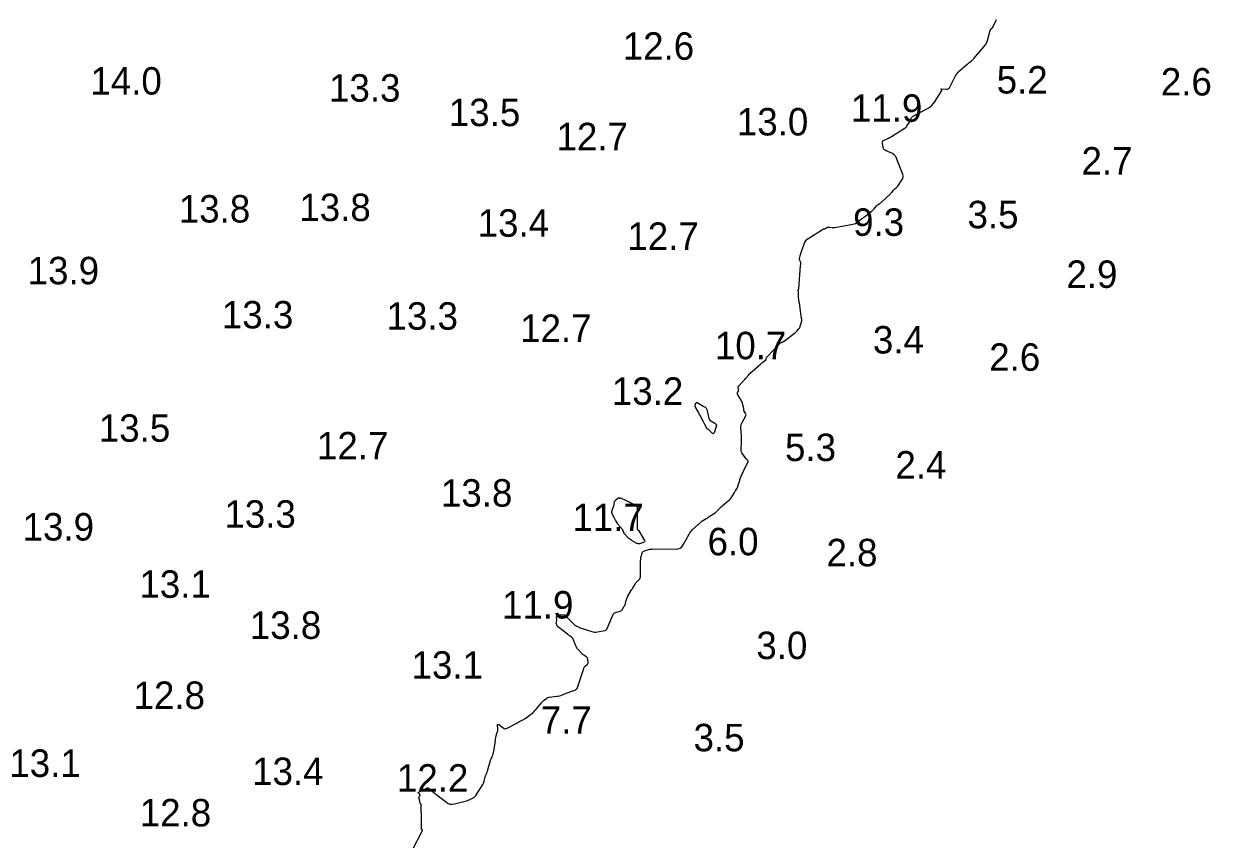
# Model space of a CAD drawing. Extents: x 815352 to 820877, y 582403 to 597439.
# Drawn here: x 819635.6 to 819851.7, y 588299.8 to 588448.3 of the extents above; entities that cross this region are included whole.
import ezdxf

# ---------------------------------------------------------------- set-up
doc = ezdxf.new("R2010")
doc.units = 0
doc.layers.add('V-CONT-EL12', color=7, linetype='Continuous')
doc.layers.add('V-TOPO-SOUN', color=7, linetype='Continuous')

msp = doc.modelspace()

# ---------------------------------------------------------------- linework, layer by layer
at = {"layer": 'V-CONT-EL12'}
msp.add_lwpolyline([(819706.36, 588297.79), (819708.22, 588301.4), (819708.23, 588301.44), (819708.23, 588301.46), (819708.22, 588301.49), (819708.2, 588301.52), (819708.08, 588301.61), (819708.05, 588301.63), (819708.03, 588301.66), (819708.02, 588301.69), (819708.02, 588301.73), (819708.05, 588302.47), (819708.05, 588302.6), (819708.06, 588302.74), (819708.06, 588302.87), (819708.05, 588303.01), (819707.95, 588306.19), (819707.95, 588306.21), (819707.94, 588306.23), (819707.93, 588306.25), (819707.91, 588306.27), (819707.83, 588306.32), (819707.81, 588306.34), (819707.79, 588306.36), (819707.78, 588306.38), (819707.77, 588306.4), (819707.58, 588307.28), (819707.57, 588307.34), (819707.57, 588307.4), (819707.59, 588307.47), (819707.61, 588307.53), (819707.74, 588307.77), (819707.76, 588307.82), (819707.76, 588307.88), (819707.75, 588307.93), (819707.71, 588307.98), (819707.49, 588308.22), (819707.45, 588308.28), (819707.45, 588308.33), (819707.47, 588308.37), (819707.52, 588308.4), (819709.02, 588309.14), (819709.06, 588309.16), (819709.09, 588309.16), (819709.13, 588309.16), (819709.17, 588309.16), (819709.33, 588309.11), (819709.37, 588309.09), (819709.4, 588309.07), (819709.44, 588309.05), (819709.47, 588309.03), (819710.27, 588308.34), (819710.42, 588308.21), (819710.56, 588308.09), (819710.71, 588307.97), (819710.86, 588307.86), (819712.56, 588306.55), (819712.9, 588306.34), (819713.26, 588306.22), (819713.64, 588306.19), (819714.04, 588306.25), (819716.24, 588306.83), (819716.4, 588306.88), (819716.55, 588306.93), (819716.71, 588306.99), (819716.85, 588307.06), (819717.45, 588307.35), (819717.59, 588307.44), (819717.71, 588307.53), (819717.82, 588307.65), (819717.92, 588307.78), (819719.18, 588309.77), (819719.26, 588309.91), (819719.33, 588310.06), (819719.39, 588310.22), (819719.44, 588310.38), (819719.62, 588311.11), (819719.65, 588311.23), (819719.69, 588311.35), (819719.73, 588311.46), (819719.77, 588311.58), (819719.97, 588312.03), (819720.02, 588312.15), (819720.06, 588312.26), (819720.1, 588312.38), (819720.14, 588312.5), (819720.54, 588313.94), (819720.58, 588314.08), (819720.63, 588314.21), (819720.68, 588314.35), (819720.73, 588314.48), (819720.96, 588315.02), (819721.01, 588315.15), (819721.05, 588315.29), (819721.09, 588315.43), (819721.12, 588315.57), (819721.42, 588317.33), (819721.44, 588317.47), (819721.47, 588317.6), (819721.49, 588317.74), (819721.51, 588317.88), (819721.6, 588318.45), (819721.62, 588318.58), (819721.65, 588318.7), (819721.68, 588318.83), (819721.72, 588318.95), (819721.87, 588319.44), (819721.91, 588319.56), (819721.93, 588319.69), (819721.93, 588319.81), (819721.93, 588319.94), (819721.88, 588320.57), (819721.89, 588320.69), (819721.93, 588320.75), (819722, 588320.75), (819722.1, 588320.7), (819722.92, 588320.1), (819723.1, 588320), (819723.28, 588319.96), (819723.47, 588319.98), (819723.66, 588320.05), (819725.28, 588320.93), (819725.43, 588321.01), (819725.58, 588321.1), (819725.74, 588321.18), (819725.89, 588321.26), (819726.51, 588321.58), (819726.66, 588321.66), (819726.81, 588321.75), (819726.96, 588321.85), (819727.1, 588321.95), (819728.14, 588322.75), (819728.35, 588322.92), (819728.55, 588323.11), (819728.75, 588323.3), (819728.93, 588323.51), (819729.92, 588324.73), (819730.02, 588324.84), (819730.12, 588324.94), (819730.23, 588325.04), (819730.34, 588325.13), (819730.81, 588325.48), (819730.94, 588325.56), (819731.06, 588325.62), (819731.2, 588325.67), (819731.34, 588325.69), (819732.65, 588325.86), (819732.9, 588325.89), (819733.15, 588325.95), (819733.39, 588326.02), (819733.63, 588326.1), (819734.74, 588326.53), (819734.9, 588326.59), (819735.06, 588326.65), (819735.22, 588326.71), (819735.38, 588326.77), (819736.02, 588327), (819736.16, 588327.07), (819736.28, 588327.17), (819736.38, 588327.29), (819736.44, 588327.44), (819737.57, 588330.94), (819737.62, 588331.06), (819737.68, 588331.17), (819737.76, 588331.27), (819737.86, 588331.36), (819738.26, 588331.71), (819738.34, 588331.8), (819738.39, 588331.9), (819738.41, 588332.02), (819738.4, 588332.14), (819738.24, 588332.81), (819738.2, 588332.91), (819738.15, 588333), (819738.08, 588333.07), (819737.98, 588333.13), (819737.58, 588333.34), (819737.49, 588333.4), (819737.4, 588333.46), (819737.31, 588333.54), (819737.24, 588333.62), (819736.55, 588334.4), (819736.45, 588334.52), (819736.36, 588334.65), (819736.28, 588334.78), (819736.22, 588334.92), (819735.91, 588335.63), (819735.87, 588335.7), (819735.84, 588335.78), (819735.81, 588335.86), (819735.78, 588335.93), (819735.66, 588336.24), (819735.63, 588336.31), (819735.59, 588336.38), (819735.53, 588336.44), (819735.47, 588336.49), (819735.03, 588336.85), (819734.93, 588336.92), (819734.84, 588337), (819734.74, 588337.07), (819734.64, 588337.15), (819733.06, 588338.36), (819733.01, 588338.4), (819732.97, 588338.43), (819732.94, 588338.47), (819732.9, 588338.52), (819732.76, 588338.7), (819732.73, 588338.74), (819732.71, 588338.78), (819732.69, 588338.81), (819732.67, 588338.85), (819732.61, 588339.01), (819732.6, 588339.05), (819732.59, 588339.09), (819732.59, 588339.13), (819732.59, 588339.17), (819732.68, 588339.68), (819732.69, 588339.74), (819732.69, 588339.79), (819732.68, 588339.85), (819732.67, 588339.91), (819732.61, 588340.13), (819732.6, 588340.18), (819732.61, 588340.24), (819732.62, 588340.29), (819732.65, 588340.33), (819732.84, 588340.57), (819732.88, 588340.61), (819732.93, 588340.64), (819732.98, 588340.66), (819733.04, 588340.67), (819733.28, 588340.67), (819733.35, 588340.67), (819733.41, 588340.68), (819733.47, 588340.68), (819733.53, 588340.69), (819733.88, 588340.72), (819733.96, 588340.72), (819734.03, 588340.71), (819734.09, 588340.68), (819734.15, 588340.63), (819734.65, 588340.14), (819734.75, 588340.04), (819734.85, 588339.94), (819734.95, 588339.84), (819735.05, 588339.74), (819735.97, 588338.83), (819736.04, 588338.77), (819736.11, 588338.72), (819736.19, 588338.67), (819736.27, 588338.63), (819736.6, 588338.48), (819736.68, 588338.45), (819736.76, 588338.41), (819736.85, 588338.38), (819736.93, 588338.35), (819739.03, 588337.65), (819739.29, 588337.58), (819739.55, 588337.54), (819739.81, 588337.55), (819740.08, 588337.58), (819741.5, 588337.86), (819741.58, 588337.89), (819741.65, 588337.93), (819741.71, 588337.98), (819741.75, 588338.04), (819741.98, 588338.46), (819741.99, 588338.48), (819742, 588338.49), (819742, 588338.5), (819742.01, 588338.52), (819742.04, 588338.59), (819742.05, 588338.62), (819742.06, 588338.63), (819742.87, 588340.63), (819742.95, 588340.8), (819743.07, 588340.93), (819743.21, 588341.03), (819743.39, 588341.11), (819744.21, 588341.35), (819744.36, 588341.4), (819744.48, 588341.48), (819744.58, 588341.59), (819744.67, 588341.72), (819744.97, 588342.27), (819745.04, 588342.41), (819745.1, 588342.56), (819745.16, 588342.7), (819745.2, 588342.86), (819745.37, 588343.5), (819745.42, 588343.65), (819745.48, 588343.8), (819745.54, 588343.95), (819745.62, 588344.09), (819746.3, 588345.24), (819746.38, 588345.37), (819746.46, 588345.5), (819746.54, 588345.63), (819746.62, 588345.76), (819746.93, 588346.28), (819747.02, 588346.41), (819747.1, 588346.52), (819747.2, 588346.64), (819747.3, 588346.74), (819747.72, 588347.16), (819747.81, 588347.27), (819747.88, 588347.4), (819747.92, 588347.53), (819747.93, 588347.67), (819747.95, 588350.62), (819747.96, 588350.79), (819747.98, 588350.96), (819748.01, 588351.13), (819748.05, 588351.29), (819748.23, 588351.94), (819748.29, 588352.09), (819748.38, 588352.21), (819748.5, 588352.3), (819748.65, 588352.36), (819749.41, 588352.58), (819749.59, 588352.62), (819749.78, 588352.65), (819749.96, 588352.67), (819750.15, 588352.68), (819754.33, 588352.66), (819754.75, 588352.7), (819755.12, 588352.85), (819755.43, 588353.1), (819755.68, 588353.45), (819756.76, 588355.39), (819756.9, 588355.61), (819757.05, 588355.82), (819757.22, 588356.01), (819757.4, 588356.2), (819758.44, 588357.13), (819758.51, 588357.19), (819758.57, 588357.25), (819758.64, 588357.31), (819758.7, 588357.37), (819758.95, 588357.61), (819759.02, 588357.67), (819759.08, 588357.72), (819759.15, 588357.78), (819759.23, 588357.82), (819759.91, 588358.23), (819760.05, 588358.31), (819760.18, 588358.39), (819760.32, 588358.48), (819760.45, 588358.57), (819761.53, 588359.29), (819761.63, 588359.36), (819761.73, 588359.44), (819761.82, 588359.53), (819761.9, 588359.62), (819762.23, 588360), (819762.32, 588360.09), (819762.41, 588360.18), (819762.5, 588360.26), (819762.59, 588360.34), (819763.96, 588361.48), (819764.11, 588361.62), (819764.24, 588361.76), (819764.37, 588361.92), (819764.48, 588362.08), (819765.02, 588362.95), (819765.06, 588363.03), (819765.11, 588363.1), (819765.16, 588363.18), (819765.21, 588363.25), (819765.4, 588363.55), (819765.45, 588363.62), (819765.49, 588363.7), (819765.53, 588363.78), (819765.56, 588363.86), (819766.16, 588365.63), (819766.27, 588365.95), (819766.39, 588366.26), (819766.53, 588366.57), (819766.67, 588366.88), (819767.51, 588368.62), (819767.53, 588368.66), (819767.53, 588368.71), (819767.51, 588368.75), (819767.48, 588368.79), (819767.33, 588368.94), (819767.3, 588368.97), (819767.26, 588369.01), (819767.23, 588369.05), (819767.19, 588369.09), (819766.5, 588369.99), (819766.39, 588370.16), (819766.31, 588370.34), (819766.27, 588370.53), (819766.26, 588370.73), (819766.31, 588372.14), (819766.32, 588372.44), (819766.31, 588372.74), (819766.3, 588373.05), (819766.29, 588373.35), (819766.19, 588374.72), (819766.19, 588374.98), (819766.23, 588375.24), (819766.3, 588375.48), (819766.41, 588375.72), (819767.08, 588376.9), (819767.13, 588377), (819767.14, 588377.11), (819767.12, 588377.21), (819767.08, 588377.32), (819766.75, 588377.89), (819766.73, 588377.92), (819766.73, 588377.95), (819766.72, 588377.98), (819766.73, 588378.01), (819766.76, 588378.14), (819766.76, 588378.17), (819766.77, 588378.2), (819766.76, 588378.24), (819766.76, 588378.27), (819766.52, 588379.17), (819766.47, 588379.33), (819766.41, 588379.49), (819766.34, 588379.64), (819766.26, 588379.78), (819765.62, 588380.78), (819765.57, 588380.86), (819765.55, 588380.95), (819765.56, 588381.04), (819765.58, 588381.13), (819765.75, 588381.55), (819765.77, 588381.61), (819765.78, 588381.68), (819765.78, 588381.74), (819765.76, 588381.81), (819765.7, 588382.08), (819765.69, 588382.14), (819765.7, 588382.2), (819765.73, 588382.26), (819765.76, 588382.31), (819766.56, 588383.15), (819766.7, 588383.3), (819766.84, 588383.46), (819766.98, 588383.61), (819767.11, 588383.77), (819767.65, 588384.4), (819767.79, 588384.56), (819767.93, 588384.71), (819768.08, 588384.85), (819768.23, 588384.99), (819769.77, 588386.34), (819769.87, 588386.43), (819769.97, 588386.51), (819770.07, 588386.59), (819770.18, 588386.67), (819770.71, 588387.07), (819770.75, 588387.11), (819770.78, 588387.15), (819770.81, 588387.2), (819770.82, 588387.25), (819770.87, 588387.47), (819770.88, 588387.53), (819770.91, 588387.58), (819770.94, 588387.62), (819770.97, 588387.67), (819773.27, 588390.1), (819773.3, 588390.13), (819773.33, 588390.15), (819773.37, 588390.18), (819773.41, 588390.2), (819773.56, 588390.28), (819773.6, 588390.3), (819773.64, 588390.32), (819773.68, 588390.34), (819773.72, 588390.36), (819773.9, 588390.44), (819773.95, 588390.46), (819773.99, 588390.48), (819774.03, 588390.51), (819774.07, 588390.54), (819775.99, 588391.98), (819776.1, 588392.07), (819776.2, 588392.16), (819776.3, 588392.25), (819776.4, 588392.35), (819776.77, 588392.77), (819776.85, 588392.88), (819776.92, 588392.99), (819776.98, 588393.11), (819777.02, 588393.24), (819777.22, 588393.96), (819777.26, 588394.13), (819777.28, 588394.29), (819777.28, 588394.46), (819777.27, 588394.63), (819776.95, 588396.95), (819776.93, 588397.12), (819776.9, 588397.3), (819776.87, 588397.47), (819776.84, 588397.64), (819776.69, 588398.51), (819776.67, 588398.59), (819776.67, 588398.68), (819776.67, 588398.76), (819776.67, 588398.85), (819776.7, 588399.23), (819776.7, 588399.3), (819776.7, 588399.36), (819776.69, 588399.42), (819776.68, 588399.48), (819776.63, 588399.79), (819776.63, 588399.82), (819776.63, 588399.85), (819776.64, 588399.88), (819776.65, 588399.91), (819776.72, 588400.02), (819776.73, 588400.05), (819776.74, 588400.08), (819776.75, 588400.11), (819776.76, 588400.14), (819777.08, 588404.22), (819777.08, 588404.27), (819777.08, 588404.32), (819777.09, 588404.37), (819777.1, 588404.42), (819777.12, 588404.63), (819777.12, 588404.68), (819777.12, 588404.73), (819777.11, 588404.77), (819777.1, 588404.82), (819776.94, 588405.22), (819776.92, 588405.31), (819776.9, 588405.39), (819776.9, 588405.48), (819776.91, 588405.56), (819777, 588406.04), (819777.02, 588406.15), (819777.05, 588406.26), (819777.08, 588406.37), (819777.11, 588406.47), (819777.74, 588408.25), (819777.88, 588408.56), (819778.07, 588408.84), (819778.3, 588409.08), (819778.57, 588409.29), (819781.07, 588410.86), (819781.12, 588410.89), (819781.16, 588410.91), (819781.21, 588410.93), (819781.26, 588410.95), (819781.47, 588411), (819781.53, 588411.01), (819781.58, 588411.03), (819781.63, 588411.05), (819781.67, 588411.08), (819781.99, 588411.26), (819782.06, 588411.29), (819782.14, 588411.31), (819782.21, 588411.32), (819782.29, 588411.31), (819782.83, 588411.24), (819782.94, 588411.23), (819783.06, 588411.23), (819783.18, 588411.23), (819783.29, 588411.25), (819786.6, 588411.81), (819786.83, 588411.86), (819787.05, 588411.94), (819787.25, 588412.05), (819787.45, 588412.19), (819788.2, 588412.78), (819788.39, 588412.93), (819788.58, 588413.08), (819788.77, 588413.23), (819788.96, 588413.37), (819790.01, 588414.19), (819790.13, 588414.28), (819790.24, 588414.39), (819790.35, 588414.5), (819790.45, 588414.61), (819790.91, 588415.17), (819790.98, 588415.24), (819791.04, 588415.31), (819791.11, 588415.36), (819791.19, 588415.42), (819791.51, 588415.62), (819791.58, 588415.67), (819791.66, 588415.72), (819791.73, 588415.78), (819791.8, 588415.84), (819793.44, 588417.38), (819793.52, 588417.45), (819793.59, 588417.53), (819793.66, 588417.6), (819793.73, 588417.68), (819794.02, 588418.03), (819794.08, 588418.1), (819794.14, 588418.16), (819794.2, 588418.22), (819794.27, 588418.27), (819794.54, 588418.49), (819794.6, 588418.54), (819794.66, 588418.6), (819794.72, 588418.67), (819794.77, 588418.74), (819795.57, 588419.94), (819795.69, 588420.17), (819795.75, 588420.4), (819795.74, 588420.65), (819795.68, 588420.89), (819794.56, 588423.87), (819794.43, 588424.13), (819794.27, 588424.35), (819794.06, 588424.53), (819793.81, 588424.67), (819792.53, 588425.24), (819792.37, 588425.34), (819792.25, 588425.46), (819792.16, 588425.61), (819792.12, 588425.79), (819792, 588426.59), (819792, 588426.77), (819792.05, 588426.92), (819792.14, 588427.04), (819792.29, 588427.13), (819792.98, 588427.45), (819793.16, 588427.53), (819793.32, 588427.62), (819793.49, 588427.71), (819793.65, 588427.81), (819795.96, 588429.26), (819796.1, 588429.35), (819796.23, 588429.46), (819796.34, 588429.58), (819796.45, 588429.71), (819796.93, 588430.35), (819796.99, 588430.43), (819797.04, 588430.52), (819797.08, 588430.61), (819797.11, 588430.71), (819797.23, 588431.11), (819797.27, 588431.2), (819797.32, 588431.28), (819797.39, 588431.35), (819797.47, 588431.41), (819800.32, 588432.96), (819800.66, 588433.18), (819800.97, 588433.43), (819801.24, 588433.73), (819801.48, 588434.05), (819802.77, 588436.06), (819802.78, 588436.1), (819802.79, 588436.14), (819802.79, 588436.18), (819802.77, 588436.22), (819802.69, 588436.38), (819802.68, 588436.42), (819802.68, 588436.44), (819802.7, 588436.46), (819802.74, 588436.46), (819803.68, 588436.4), (819803.84, 588436.41), (819803.98, 588436.46), (819804.09, 588436.55), (819804.18, 588436.68), (819805.21, 588438.71), (819805.37, 588439), (819805.57, 588439.28), (819805.79, 588439.53), (819806.04, 588439.77), (819807.41, 588440.94), (819807.51, 588441.02), (819807.61, 588441.11), (819807.71, 588441.19), (819807.82, 588441.27), (819808.23, 588441.6), (819808.33, 588441.69), (819808.43, 588441.78), (819808.52, 588441.87), (819808.61, 588441.97), (819810.48, 588444.14), (819810.69, 588444.4), (819810.86, 588444.67), (819810.99, 588444.97), (819811.1, 588445.28), (819811.59, 588447.08), (819811.62, 588447.14), (819811.65, 588447.2), (819811.68, 588447.25), (819811.73, 588447.3), (819811.93, 588447.49), (819811.98, 588447.54), (819812.02, 588447.59), (819812.05, 588447.64), (819812.08, 588447.7), (819812.73, 588449.12)], dxfattribs=at)
for points in [[(819760.26, 588374.44), (819760.23, 588374.46), (819760.21, 588374.49), (819760.18, 588374.51), (819760.07, 588374.58), (819760.04, 588374.6), (819760.02, 588374.63), (819760, 588374.65), (819759.98, 588374.68), (819759.64, 588375.33), (819759.58, 588375.45), (819759.52, 588375.57), (819759.46, 588375.69), (819759.4, 588375.81), (819758.71, 588377.12), (819758.63, 588377.28), (819758.54, 588377.43), (819758.46, 588377.59), (819758.37, 588377.75), (819757.95, 588378.51), (819757.91, 588378.6), (819757.89, 588378.69), (819757.89, 588378.78), (819757.9, 588378.88), (819758.01, 588379.26), (819758.04, 588379.34), (819758.09, 588379.38), (819758.15, 588379.38), (819758.23, 588379.35), (819759.48, 588378.64), (819759.69, 588378.49), (819759.86, 588378.31), (819759.98, 588378.09), (819760.05, 588377.84), (819760.28, 588376.66), (819760.34, 588376.46), (819760.43, 588376.29), (819760.56, 588376.14), (819760.73, 588376.02), (819761.47, 588375.59), (819761.63, 588375.47), (819761.72, 588375.32), (819761.74, 588375.16), (819761.7, 588374.97), (819761.31, 588373.84), (819761.24, 588373.72), (819761.16, 588373.66), (819761.07, 588373.68), (819760.96, 588373.76), (819760.28, 588374.42)], [(819746.6, 588354.05), (819746.51, 588354.1), (819746.42, 588354.16), (819746.33, 588354.21), (819745.97, 588354.44), (819745.89, 588354.5), (819745.8, 588354.56), (819745.73, 588354.63), (819745.66, 588354.71), (819745, 588355.45), (819744.96, 588355.51), (819744.92, 588355.56), (819744.89, 588355.63), (819744.87, 588355.69), (819744.79, 588355.96), (819744.76, 588356.02), (819744.73, 588356.08), (819744.69, 588356.14), (819744.65, 588356.2), (819744.14, 588356.79), (819744.04, 588356.91), (819743.95, 588357.04), (819743.86, 588357.16), (819743.77, 588357.29), (819743.36, 588357.95), (819743.29, 588358.07), (819743.22, 588358.19), (819743.16, 588358.31), (819743.1, 588358.43), (819742.76, 588359.11), (819742.75, 588359.14), (819742.74, 588359.17), (819742.73, 588359.21), (819742.72, 588359.24), (819742.69, 588359.37), (819742.69, 588359.41), (819742.69, 588359.44), (819742.69, 588359.47), (819742.7, 588359.5), (819743.02, 588360.43), (819743.05, 588360.53), (819743.08, 588360.62), (819743.1, 588360.72), (819743.12, 588360.82), (819743.18, 588361.22), (819743.2, 588361.32), (819743.24, 588361.41), (819743.29, 588361.48), (819743.36, 588361.56), (819743.88, 588362.01), (819743.9, 588362.02), (819743.93, 588362.03), (819743.95, 588362.02), (819743.97, 588362.01), (819744.09, 588361.93), (819744.11, 588361.92), (819744.12, 588361.92), (819744.13, 588361.92), (819744.15, 588361.93), (819744.2, 588361.96), (819744.21, 588361.97), (819744.23, 588361.97), (819744.24, 588361.97), (819744.25, 588361.97), (819745.32, 588361.51), (819745.5, 588361.43), (819745.67, 588361.34), (819745.85, 588361.25), (819746.02, 588361.16), (819747.04, 588360.57), (819747.07, 588360.54), (819747.11, 588360.52), (819747.14, 588360.49), (819747.17, 588360.46), (819747.31, 588360.3), (819747.33, 588360.28), (819747.34, 588360.25), (819747.35, 588360.22), (819747.35, 588360.19), (819747.34, 588360.07), (819747.34, 588360.04), (819747.34, 588360.01), (819747.34, 588359.98), (819747.34, 588359.95), (819747.3, 588356.36), (819747.31, 588356.32), (819747.32, 588356.28), (819747.34, 588356.25), (819747.37, 588356.22), (819747.52, 588356.12), (819747.55, 588356.09), (819747.58, 588356.06), (819747.61, 588356.03), (819747.63, 588355.99), (819748.63, 588354.23), (819748.68, 588354.1), (819748.67, 588353.99), (819748.6, 588353.9), (819748.47, 588353.84), (819747.76, 588353.64), (819747.63, 588353.62), (819747.5, 588353.62), (819747.37, 588353.65), (819747.24, 588353.7), (819746.69, 588354)]]:
    msp.add_lwpolyline(points, close=True, dxfattribs=at)

# ---------------------------------------------------------------- texts
at = {"layer": 'V-TOPO-SOUN'}
for s, p in [('12.6 ', (819744.68, 588441.76)), ('14.0 ', (819647.72, 588435.42)), ('5.2', (819812.79, 588435.62)), ('13.3 ', (819691.19, 588434.14)), ('2.6', (819842.69, 588435.26)), ('13.5 ', (819713.01, 588429.68)), ('11.9 ', (819786.24, 588430.47)), ('13.0 ', (819765.47, 588427.98)), ('12.7 ', (819732.63, 588425.29)), ('2.7', (819828.25, 588420.86)), ('13.8 ', (819663.83, 588412.13)), ('13.8 ', (819685.78, 588412.39)), ('13.4 ', (819718.26, 588409.54)), ('9.3', (819786.64, 588409.7)), ('3.5', (819807.48, 588411.08)), ('12.7 ', (819745.52, 588407.14)), ('13.9 ', (819636.3, 588400.88)), ('2.9', (819825.49, 588400.22)), ('13.3 ', (819671.67, 588392.84)), ('13.3 ', (819701.66, 588392.61)), ('12.7 ', (819726, 588390.38)), ('3.4', (819790.25, 588388.28)), ('10.7 ', (819761.47, 588387.23)), ('2.6', (819811.43, 588385.13)), ('13.2 ', (819742.7, 588378.93)), ('13.5 ', (819649.26, 588372.2)), ('12.7 ', (819688.99, 588368.99)), ('5.3', (819774.24, 588368.69)), ('2.4', (819794.35, 588365.51)), ('13.8 ', (819711.57, 588360.39)), ('13.3 ', (819672.13, 588356.55)), ('11.7 ', (819735.52, 588355.93)), ('13.9 ', (819635.38, 588354.22)), ('6.0', (819760.13, 588351.53)), ('2.8', (819781.79, 588349.53)), ('13.1 ', (819656.65, 588343.79)), ('11.9 ', (819722.69, 588340.02)), ('13.8 ', (819676.76, 588336.31)), ('3.0', (819769.02, 588332.63)), ('13.1 ', (819706.22, 588329.06)), ('12.8 ', (819655.59, 588323.55)), ('7.7', (819729.75, 588319.05)), ('3.5', (819757.58, 588315.84)), ('13.1 ', (819632.96, 588311.18)), ('13.4 ', (819677.18, 588309.7)), ('12.2 ', (819703.56, 588308.49)), ('12.8 ', (819656.71, 588302.16))]:
    msp.add_text(s, height=5, dxfattribs=at).set_placement(p)

doc.saveas('drawing.dxf')
